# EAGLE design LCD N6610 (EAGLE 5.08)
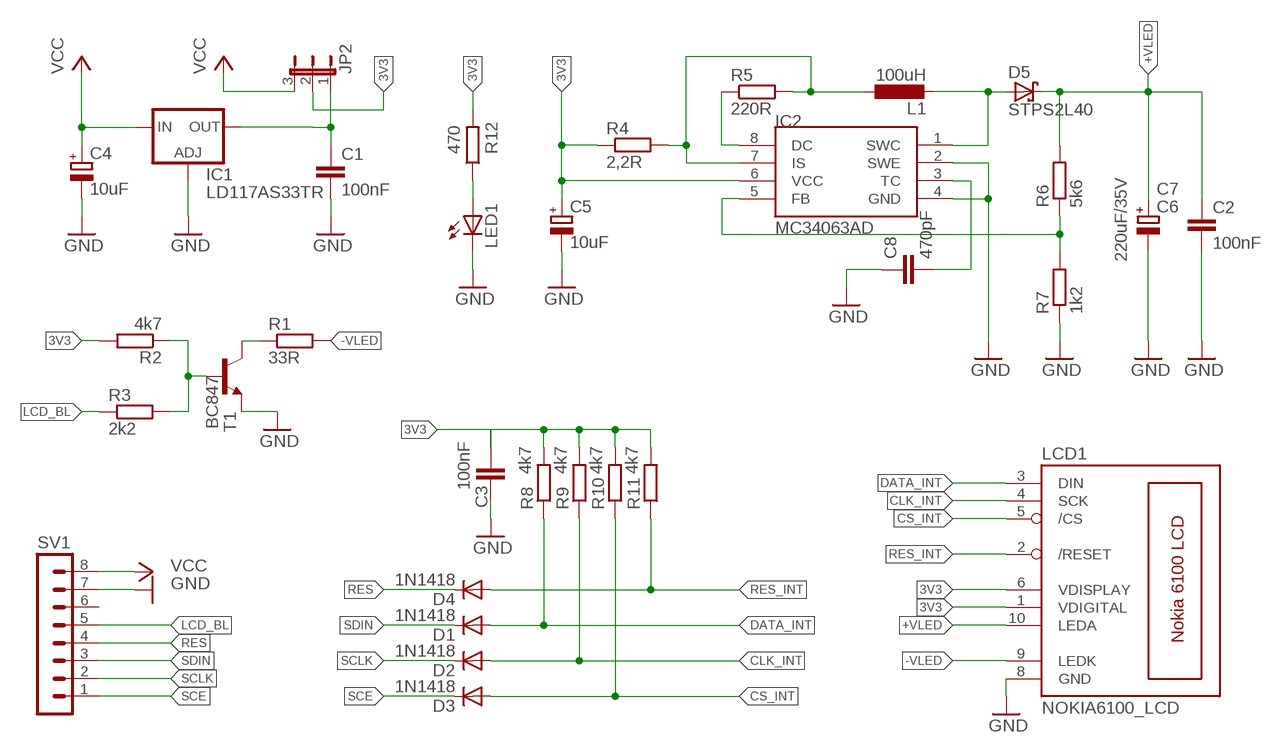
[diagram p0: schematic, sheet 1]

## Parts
C1  100nF  C-EUC1206  [C1206]
C2  100nF  C-EUC1206  [C1206]
C3  100nF  C-EUC1206  [C1206]
C4  10uF  CPOL-EUSMCB  [SMC_B]
C5  10uF  CPOL-EUSMCB  [SMC_B]
C6  CPOL-EUSMCE  [SMC_E]
C7  220uF/35V  CPOL-EUSMCE  [SMC_E]
C8  470pF  C-EUC1206  [C1206]
D1  1N1418  BAT81  [DO34-7]
D2  1N1418  BAT81  [DO34-7]
D3  1N1418  BAT81  [DO34-7]
D4  1N1418  BAT81  [DO34-7]
D5  STPS2L40  MBRS130LT3  [SMB]
IC1  LD117AS33TR  [SOT223]
IC2  MC34063AD  [SOIC8]
JP2  JP2E  [JP2]
L1  100uH  L-EUL5038P  [L5038P]
LCD1  NOKIA6100_LCD  [NOKIA6100_LCD]
LED1  LEDCHIPLED_1206  [CHIPLED_1206]
R1  33R  R-EU_R1206  [R1206]
R2  4k7  R-EU_R1206  [R1206]
R3  2k2  R-EU_R1206  [R1206]
R4  2,2R  R-EU_R1206  [R1206]
R5  220R  R-EU_R1206  [R1206]
R6  5k6  R-EU_R1206  [R1206]
R7  1k2  R-EU_R1206  [R1206]
R8  4k7  R-EU_R1206  [R1206]
R9  4k7  R-EU_R1206  [R1206]
R10  4k7  R-EU_R1206  [R1206]
R11  4k7  R-EU_R1206  [R1206]
R12  470  R-EU_R1206  [R1206]
SV1  MA08-1  [MA08-1]
T1  BC847  [SOT23]

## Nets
3,3V: C1.1 IC1.4(OUT) JP2.1
3V3: C3.1 C5.+ IC2.6(VCC) JP2.2 LCD1.1(VDIGITAL) LCD1.6(VDISPLAY) R2.2 R4.1 R8.2 R9.2 R10.2 R11.2 R12.2
+VLED: C2.1 C6.+ C7.+ D5.C LCD1.10(LEDA) R6.2
-VLED: LCD1.9(LEDK) R1.2
CLK_INT: D2.A LCD1.4(SCK) R9.1
CS_INT: D3.A LCD1.5(/CS) R10.1
DATA_INT: D1.A LCD1.3(DIN) R8.1
GND: C1.2 C2.2 C3.2 C4.- C5.- C6.- C7.- C8.1 IC1.1(ADJ) IC2.2(SWE) IC2.4(GND) LCD1.8(GND) LED1.C R7.1 SV1.7 T1.2(E)
LCD_BL: R3.1 SV1.5
N$1: R2.1 R3.2 T1.1(B)
N$2: R1.1 T1.3(C)
N$3: IC2.5(FB) R6.1 R7.2
N$4: IC2.7(IS) L1.1 R4.2 R5.2
N$5: IC2.8(DC) R5.1
N$6: C8.2 IC2.3(TC)
N$7: D5.A IC2.1(SWC) L1.2
N$8: LED1.A R12.1
RES: D4.C SV1.4
RES_INT: D4.A LCD1.2(/RESET) R11.1
SCE: D3.C SV1.1
SCLK: D2.C SV1.2
SDIN: D1.C SV1.3
VCC: C4.+ IC1.3(IN) JP2.3 SV1.8
Unconnected: SV1.6

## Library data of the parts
C1-C3 C8 = rcl:C-EU: CAPACITOR, European symbol
C4-C7 = rcl:CPOL-EU: POLARIZED CAPACITOR, European symbol
D1-D4 = diode:BAT81: DIODE
D5 = diode:MBRS130LT3: Schottky Power Rectifier
IC1 = v-reg:LD117A?*: Low drop fixed and adjustable positive voltage regulators 1 A Source: http://www.st.com/stonline/products/literature/ds/7194/ld1117axx.pdf
IC2 = mc34063:MC34063
JP2 = jumper:JP2E: JUMPER
L1 = rcl:L-EU: INDUCTOR, European symbol
LCD1 = lcd_nokia_6100:NOKIA6100_LCD
LED1 = led:LED: LED
R1-R12 = rcl:R-EU_: RESISTOR, European symbol
SV1 = con-lstb:MA08-1: PIN HEADER
T1 = transistor:BC847: NPN TRANSISTOR

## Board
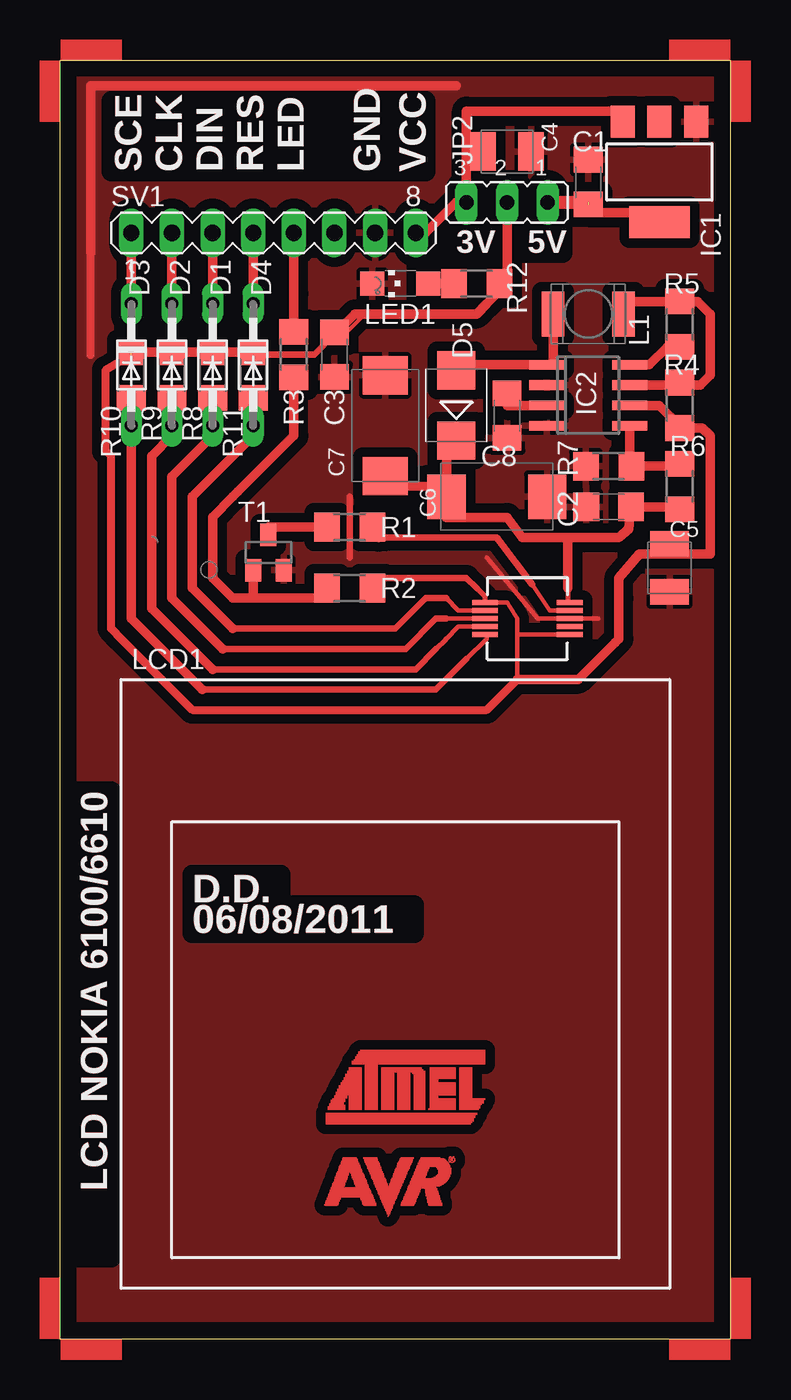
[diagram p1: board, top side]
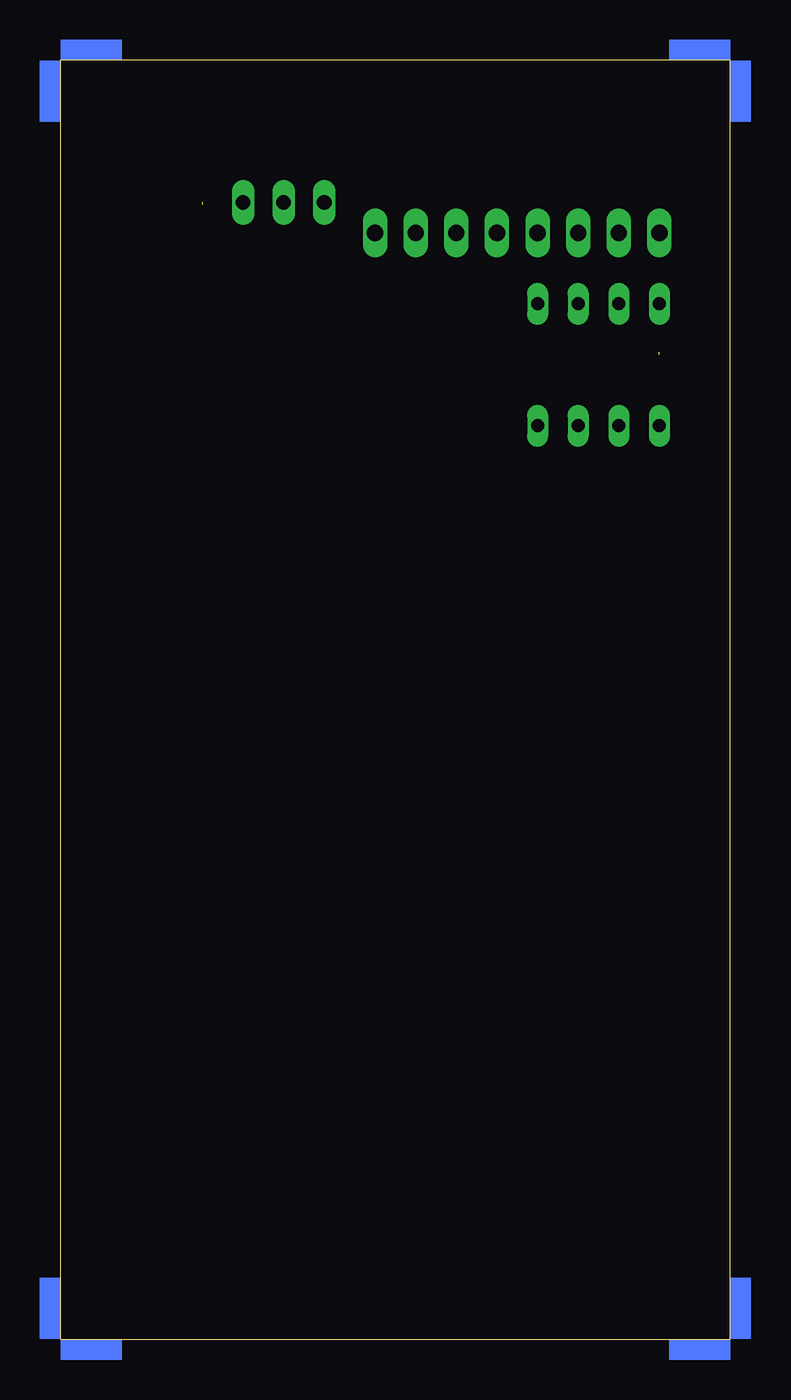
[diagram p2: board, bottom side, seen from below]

Size 41.91 x 80.01 mm. Coordinates in mm from the lower left corner, seen from the top.
Outline: 0,80.01 41.91,80.01 41.91,0 0,0 0,80.01
Copper layers (1*16): Top 0.035mm / dielectric 1.5mm / Bottom 0.035mm
Design rules "default": minimum track width 10mil, minimum drill 24mil, track to track 8mil, track to pad 8mil, pad to pad 8mil, via to via 8mil, smd to smd 8mil, copper to edge 40mil, drill to drill 8mil, minimum pad ring 10mil, minimum via ring 8mil, stop-mask expansion 4mil, vias tented up to drill 0mil, thermal gap 10mil
tRestrict: area 3.2,73 to 22.9,77.5; area 1.3,5.1 to 3.2,34.3

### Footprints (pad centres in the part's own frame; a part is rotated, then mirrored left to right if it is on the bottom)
C1206 = smd 1.6 x 1.8: 1 -1.4,0; 2 1.4,0
SMC_B = smd 1.6 x 2.4: + -1.5,0; - 1.5,0
SMC_E = smd 2.4 x 2.8: + -3.15,0; - 3.15,0
DO34-7 = drill 0.813 long: A 3.81,0; C -3.81,0
SMB = smd 2.4 x 2.4: A 2.2,0; C -2.2,0
SOT223 = smd 1.5 x 2: 1 -2.3,-3.15; 2 0,-3.15; 3 2.3,-3.15 | smd 3.8 x 2: 4 0,3.15
SOIC8 = smd 0.6 x 2.2: 1 -1.905,-2.6; 2 -0.635,-2.6; 3 0.635,-2.6; 4 1.905,-2.6; 5 1.905,2.6; 6 0.635,2.6; 7 -0.635,2.6; 8 -1.905,2.6
JP2 = drill 0.914 long: 1 -2.54,0; 2 0,0; 3 2.54,0
L5038P = smd 1.4 x 2.8: 1 -2.2,0; 2 2.2,0
NOKIA6100_LCD = smd 1.6 x 0.3: 1 -2.65,1; 2 -2.65,0.5; 3 -2.65,0; 4 -2.65,-0.5; 5 -2.65,-1; 6 2.65,-1; 7 2.65,-0.5; 8 2.65,0; 9 2.65,0.5; 10 2.65,1
CHIPLED_1206 = smd 1.5 x 1.5: A 0,-1.75; C 0,1.75
R1206 = smd 1.6 x 1.803: 1 -1.422,0; 2 1.422,0
MA08-1 = drill 1.016 long: 1 -8.89,0; 2 -6.35,0; 3 -3.81,0; 4 -1.27,0; 5 1.27,0; 6 3.81,0; 7 6.35,0; 8 8.89,0
SOT23 = smd 1 x 1.4: 1 -0.95,-1.1; 2 0.95,-1.1; 3 0,1.1

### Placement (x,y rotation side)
C1  33.02,72.39 90 top
C2  34.29,52.07 180 top
C3  17.14,61.59 270 top
C4  27.94,74.3 0 top
C5  38.1,48.26 270 top
C6  27.3,52.7 0 top
C7  20.32,57.15 90 top
C8  27.94,57.78 90 top
D1  9.53,60.96 270 top
D2  6.99,60.96 270 top
D3  4.45,60.96 270 top
D4  12.06,60.96 270 top
D5  24.77,58.42 90 top
IC1  37.47,73.03 180 top
IC2  33.02,59.05 270 top
JP2  27.94,71.12 180 top
L1  33.02,64.14 180 top
LCD1  29.21,45.09 0 top
LED1  21.27,66.04 90 top
R1  18.1,50.8 0 top
R2  18.1,46.99 0 top
R3  14.61,61.59 270 top
R4  38.73,58.42 90 top
R5  38.73,63.5 90 top
R6  38.73,53.34 270 top
R7  34.29,54.61 0 top
R8  9.53,60.33 90 top
R9  6.99,60.33 90 top
R10  4.45,60.33 90 top
R11  12.06,60.33 90 top
R12  26.04,66.04 0 top
SV1  13.34,69.22 0 top
T1  13.02,49.21 0 top
U$1  [ANGLE-SE1-16]  0,80.01 270 top
U$2  [ANGLE-SE1-16]  41.91,80.01 180 top
U$3  [ANGLE-SE1-16]  41.91,0 90 top
U$4  [ANGLE-SE1-16]  0,0 0 top
U$5  [LOGO]  1.91,47.62 0 top

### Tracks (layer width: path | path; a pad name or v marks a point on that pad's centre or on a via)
3,3V  (1 unrouted)
  Top 0.61: IC1.4 36.8,69.85 36.2,70.48 33.02,70.48 C1.1
  Top 0.813: JP2.1 31.11,71.12 31.75,71.12 33.02,71.12
3V3  (1 unrouted)
  Top 0.254: 19.05,64.14 17.78,62.87 C3.1 | R10.2 3.81,61.59
  Top 0.279: LCD1.6 28.57,44.09 28.57,44.45 | 28.57,44.45 28.57,45.09 27.94,46.09 LCD1.1 | 28.57,41.27 28.57,44.45
  Top 0.305: LCD1.1 26.56,46.47 26.04,46.99
  Top 0.406: R2.2 20,46.99 19.37,46.99 20,47.62 22.23,47.62 24.13,47.62 25.4,47.62 26.04,46.99 | 17.14,62.87 15.88,61.59 12.22,61.59 R11.2
  Top 0.508: 28.57,41.27 26.67,39.37 8.26,39.37 6.35,41.27 3.81,43.81 3.17,44.45 3.17,45.72 3.17,55.24 2.86,55.56 2.86,60.64 4.45,61.59 | 10.64,61.75 R11.2
  Top 0.61: 10.64,61.75 R8.2 R9.2 R10.2 4.42,61.73 | 10.64,61.75 R11.2 10.64,61.75 | 35.56,58.42 IC2.6 37.47,58.42 38.73,57.15 R4.1 40.16,57 40.64,56.52 40.64,50.16 40.64,49.12 38.1,49.12 | 17.14,62.87 18.41,64.14 | 18.41,64.14 18.73,64.14 | 18.41,64.14 18.73,64.14 | 18.41,64.14 18.73,64.14 | 18.73,64.14 19.05,64.14 22.23,64.14 23.5,64.14 26.04,64.14 26.67,64.77 27.62,65.72 | 38.1,49.12 36.2,49.12 34.92,47.62 34.92,46.35 34.92,43.81 34.7,43.59 32.38,41.27 28.57,41.27 | 38.1,49.12 C5.+ | 27.62,65.72 27.94,66.04 JP2.2 | 27.62,65.72 R12.2
+VLED
  Top 0.279: LCD1.10 31.8,46.09
  Top 0.305: 31.75,46.99 31.75,46.09 LCD1.10
  Top 0.61: 31.75,50.14 34.92,50.14 | 31.75,50.14 31.75,46.99 | 31.75,50.14 28.92,50.14 28.89,50.16 27.94,51.41 24.13,51.41 24.13,53.34 24.13,52.7 C6.+ | 31.75,50.14 34.92,50.14 | R6.2 38.58,52.07 C2.1 35.56,50.67 34.92,50.14 | C7.+ 20.32,53.34 20.95,53.34 24.18,53.37 C6.+ | C6.+ 24.16,55.61 D5.C
-VLED
  Top 0.279: LCD1.9 30.61,45.59 29.52,47.22
  Top 0.406: 29.52,47.22 27.3,50.16 19.9,50.16
  Top 0.61: 19.9,50.16 R1.2
CLK_INT
  Top 0.279: LCD1.4 24.9,44.59 24.13,43.81
  Top 0.305: 23.5,43.18 24.13,43.81
  Top 0.406: 23.5,43.18 22.23,41.91 9.53,41.91 | 6.99,56.52 D2.A
  Top 0.61: 6.99,56.52 5.71,55.24 5.71,45.72 9.53,41.91 | D2.A R9.1
CS_INT
  Top 0.279: 25.4,42.55 26.67,43.81 26.67,44.09 LCD1.5
  Top 0.406: 25.4,42.55 23.5,40.64 8.89,40.64
  Top 0.61: 8.89,40.64 4.45,45.09 4.45,50.8 4.45,54.61 D3.A R10.1
DATA_INT
  Top 0.279: 24.13,45.09 LCD1.3
  Top 0.406: 24.13,45.09 23.5,45.09 21.59,43.18 10.16,43.18 | 9.53,56.52 D1.A
  Top 0.61: 9.53,56.52 6.99,53.98 6.99,46.35 10.16,43.18 | D1.A R8.1
GND
  Top 0.279: LCD1.8 29.84,45.09 26.67,48.9 | LCD1.8 33.66,45.09 LCD1.8
  Top 0.406: 18.1,48.9 18.1,52.7
  Top 0.508: 1.91,61.59 1.91,67.94
  Top 0.61: 1.91,67.94 1.91,72.39 1.91,78.42 17.78,78.42 24.77,78.42
  pour Top (isolate 0.61): -1.27,80.64 44.45,79.38 45.09,1.27 -1.91,1.27
LCD_BL
  Top 0.61: R3.1 14.61,62.87 14.61,65.41 SV1.5
N$1
  Top 0.406: R2.1 16.19,46.35 11.43,46.35 12.07,46.36 12.07,46.67 | 10.79,52.7 11.11,53.02 10.79,52.7
  Top 0.61: R3.2 14.61,56.52 11.11,53.02 10.79,52.7 9.53,51.44 9.53,47.62 10.79,46.35 11.43,46.35 16.19,46.35 | 12.07,46.67 T1.1
N$2
  Top 0.61: R1.1 13.02,50.8 T1.3
N$3
  Top 0.61: 36.2,57.15 IC2.5 35.62,54.7 R7.2 38.58,54.61 R6.1
N$4
  Top 0.61: IC2.7 38.58,59.69 R4.2 38.89,59.69 40.01,59.69 40.64,60.33 40.64,64.14 39.85,64.92 R5.2 35.71,64.92 35.56,64.77 35.56,64.47 L1.1
N$5
  Top 0.61: R5.1 37.95,62.08 36.83,60.96 IC2.8
N$6
  Top 0.61: IC2.3 27.94,58.42 C8.2
N$7
  Top 0.61: L1.2 30.82,61.26 31.11,60.96 IC2.1 25.11,60.96 D5.A
N$8
  Top 0.61: R12.1 LED1.A
RES
  Top 0.61: D4.C SV1.4
RES_INT
  Top 0.279: LCD1.2 24.9,45.59 24.13,46.35
  Top 0.406: 24.13,46.35 23.5,46.35 22.86,46.35 20.95,44.45 10.79,44.45 | 12.06,56.52 D4.A
  Top 0.61: 12.06,56.52 8.26,52.7 8.26,46.99 10.79,44.45 | D4.A R11.1
SCE
  Top 0.61: D3.C SV1.1 D3.C
SCLK
  Top 0.61: D2.C SV1.2
SDIN
  Top 0.61: D1.C SV1.3
VCC
  Top 0.61: SV1.8 22.86,69.22 24.77,71.12 JP2.3 25.4,71.75 25.4,74.3 | 25.4,74.3 25.4,76.83 35.16,76.83 IC1.3 | 25.4,74.3 C4.+
(copper drawn outside any net)
  shapes: Top area x518

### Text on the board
Top: SCE | CLK | DIN | RES | LED | GND | VCC | 3V | 5V | LCD NOKIA 6100/6610 | D.D. | 06/08/2011
tPlace: SCE | CLK | DIN | RES | LED | GND | VCC | 3V | 5V | LCD NOKIA 6100/6610 | D.D. | 06/08/2011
